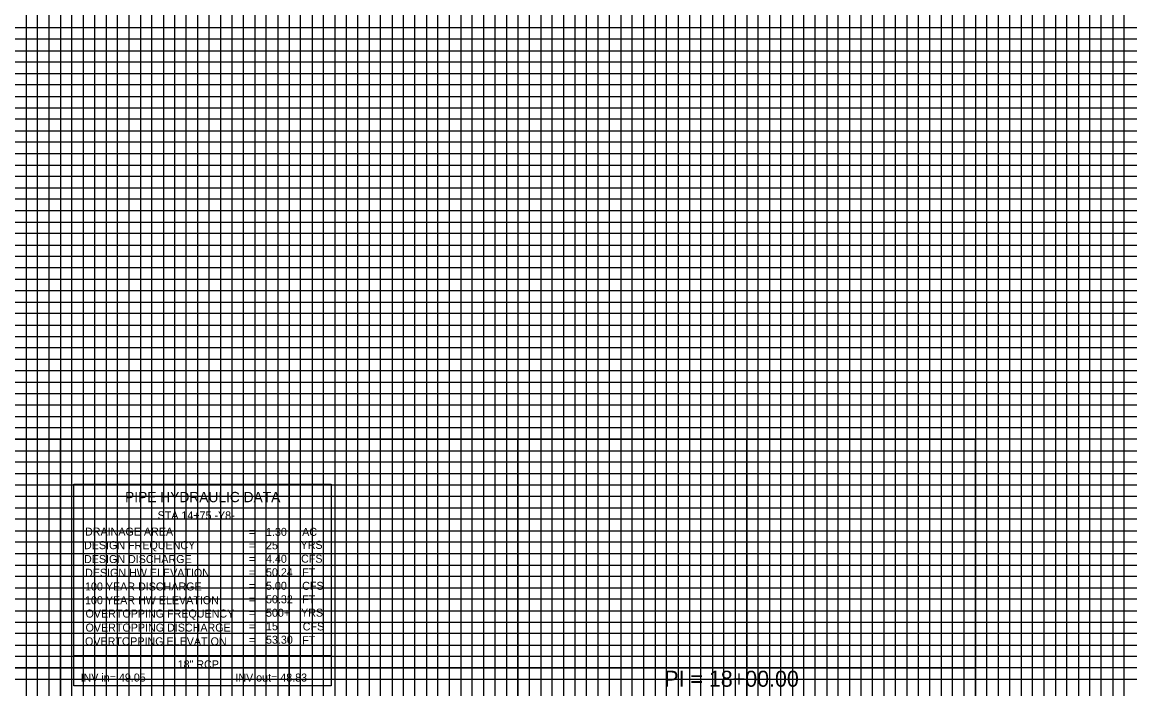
# Model space of a CAD drawing. Extents: x 2345490 to 2436403, y 465165 to 573888.
# Drawn here: x 2382250.1 to 2382734.3, y 541265.3 to 541557 of the extents above; entities that cross this region are included whole.
import ezdxf

# ---------------------------------------------------------------- set-up
doc = ezdxf.new("R2010")
doc.units = 0
for name, color, linetype in [('Old_Level_2', 7, 'Continuous'), ('Old_Level_4', 7, 'Continuous'), ('Old_Level_41', 7, 'Continuous'), ('Old_Level_42', 7, 'Continuous'), ('Old_Level_43', 7, 'Continuous'), ('Old_Level_57', 7, 'Continuous')]:
    doc.layers.add(name, color=color, linetype=linetype)

msp = doc.modelspace()

# ---------------------------------------------------------------- linework, layer by layer
at = {"layer": 'Old_Level_4'}
for p, q in [((2382272.67092, 541354.8205), (2382385.17092, 541354.8205)), ((2382272.67092, 541279.8205), (2382272.67092, 541354.8205)), ((2382385.17092, 541354.8205), (2382385.17092, 541279.8205)), ((2382385.17092, 541279.8205), (2382272.67092, 541279.8205))]:
    msp.add_line(p, q, dxfattribs=at)
msp.add_lwpolyline([(2382272.67092, 541279.8205), (2382385.17092, 541279.8205), (2382385.17092, 541266.6055), (2382272.67092, 541266.6055)], close=True, dxfattribs=at)
at = {"layer": 'Old_Level_41'}
for points in [[(2382241.79875, 541024.5045), (2382291.79875, 541024.5045), (2382291.79875, 542049.5045)], [(2382266.79875, 542049.5045), (2382266.79875, 541024.5045), (2382316.79875, 541024.5045), (2382316.79875, 542049.5045)], [(2382341.79875, 542049.5045), (2382341.79875, 541024.5045), (2382391.79875, 541024.5045), (2382391.79875, 542049.5045)], [(2382366.79875, 542049.5045), (2382366.79875, 541024.5045), (2382416.79875, 541024.5045), (2382416.79875, 542049.5045)], [(2382441.79875, 542049.5045), (2382441.79875, 541024.5045), (2382491.79875, 541024.5045), (2382491.79875, 542049.5045)], [(2382466.79875, 542049.5045), (2382466.79875, 541024.5045), (2382516.79875, 541024.5045), (2382516.79875, 542049.5045)], [(2382541.79875, 542049.5045), (2382541.79875, 541024.5045), (2382591.79875, 541024.5045), (2382591.79875, 542049.5045)], [(2382566.79875, 542049.5045), (2382566.79875, 541024.5045), (2382616.79875, 541024.5045), (2382616.79875, 542049.5045)], [(2382641.79875, 542049.5045), (2382641.79875, 541024.5045), (2382691.79875, 541024.5045), (2382691.79875, 542049.5045)], [(2382666.79875, 542049.5045), (2382666.79875, 541024.5045), (2382716.79875, 541024.5045), (2382716.79875, 542049.5045)], [(2383216.79875, 541549.5045), (2381716.79875, 541549.5045), (2381716.79875, 541499.5045), (2383216.79875, 541499.5045)], [(2383216.79875, 541449.5045), (2381716.79875, 541449.5045), (2381716.79875, 541399.5045), (2383216.79875, 541399.5045)], [(2383216.79875, 541374.5045), (2381716.79875, 541374.5045), (2381716.79875, 541424.5045), (2383216.79875, 541424.5045)], [(2383216.79875, 541349.5045), (2381716.79875, 541349.5045), (2381716.79875, 541299.5045), (2383216.79875, 541299.5045)], [(2383216.79875, 541274.5045), (2381716.79875, 541274.5045), (2381716.79875, 541324.5045), (2383216.79875, 541324.5045)]]:
    msp.add_lwpolyline(points, dxfattribs=at)
at = {"layer": 'Old_Level_42'}
msp.add_lwpolyline([(2383216.79875, 541474.5045), (2381716.79875, 541474.5045), (2381716.79875, 541524.5045), (2383216.79875, 541524.5045)], dxfattribs=at)
at = {"layer": 'Old_Level_43'}
for points in [[(2382251.79875, 542049.5045), (2382251.79875, 541024.5045), (2382256.79875, 541024.5045), (2382256.79875, 542049.5045), (2382261.79875, 542049.5045), (2382261.79875, 541024.5045), (2382271.79875, 541024.5045), (2382271.79875, 542049.5045), (2382276.79875, 542049.5045), (2382276.79875, 541024.5045), (2382281.79875, 541024.5045), (2382281.79875, 542049.5045), (2382286.79875, 542049.5045), (2382286.79875, 541024.5045)], [(2382296.79875, 541024.5045), (2382296.79875, 542049.5045)], [(2382301.79875, 542049.5045), (2382301.79875, 541024.5045), (2382306.79875, 541024.5045), (2382306.79875, 542049.5045)], [(2382311.79875, 542049.5045), (2382311.79875, 541024.5045), (2382321.79875, 541024.5045), (2382321.79875, 542049.5045)], [(2382326.79875, 542049.5045), (2382326.79875, 541024.5045), (2382326.79875, 541024.5045), (2382331.79875, 541024.5045), (2382331.79875, 542049.5045)], [(2382336.79875, 542049.5045), (2382336.79875, 541024.5045), (2382346.79875, 541024.5045), (2382346.79875, 542049.5045)], [(2382351.79875, 542049.5045), (2382351.79875, 541024.5045), (2382356.79875, 541024.5045), (2382356.79875, 542049.5045)], [(2382361.79875, 542049.5045), (2382361.79875, 541024.5045), (2382371.79875, 541024.5045), (2382371.79875, 542049.5045)], [(2382376.79875, 542049.5045), (2382376.79875, 541024.5045), (2382381.79875, 541024.5045), (2382381.79875, 542049.5045)], [(2382386.79875, 542049.5045), (2382386.79875, 541024.5045), (2382396.79875, 541024.5045), (2382396.79875, 542049.5045)], [(2382401.79875, 542049.5045), (2382401.79875, 541024.5045), (2382406.79875, 541024.5045), (2382406.79875, 542049.5045)], [(2382411.79875, 542049.5045), (2382411.79875, 541024.5045), (2382421.79875, 541024.5045), (2382421.79875, 542049.5045)], [(2382426.79875, 542049.5045), (2382426.79875, 541024.5045), (2382431.79875, 541024.5045), (2382431.79875, 542049.5045)], [(2382436.79875, 542049.5045), (2382436.79875, 541024.5045), (2382446.79875, 541024.5045), (2382446.79875, 542049.5045)], [(2382451.79875, 542049.5045), (2382451.79875, 541024.5045), (2382456.79875, 541024.5045), (2382456.79875, 542049.5045)], [(2382461.79875, 542049.5045), (2382461.79875, 541024.5045), (2382471.79875, 541024.5045), (2382471.79875, 542049.5045)], [(2382476.79875, 542049.5045), (2382476.79875, 541024.5045)], [(2382476.79875, 541024.5045), (2382481.79875, 541024.5045), (2382481.79875, 542048.9045)], [(2382486.79875, 542048.9045), (2382486.79875, 541024.5045), (2382496.79875, 541024.5045), (2382496.79875, 542049.5045)], [(2382501.79875, 542049.5045), (2382501.79875, 541024.5045), (2382506.79875, 541024.5045), (2382506.79875, 542049.5045)], [(2382511.79875, 542049.5045), (2382511.79875, 541024.5045), (2382521.79875, 541024.5045), (2382521.79875, 542049.5045)], [(2382526.79875, 542049.5045), (2382526.79875, 541024.5045), (2382531.79875, 541024.5045), (2382531.79875, 542049.5045)], [(2382536.79875, 542049.5045), (2382536.79875, 541024.5045), (2382546.79875, 541024.5045), (2382546.79875, 542049.5045)], [(2382551.79875, 542049.5045), (2382551.79875, 541024.5045), (2382556.79875, 541024.5045), (2382556.79875, 542049.5045)], [(2382561.79875, 542049.5045), (2382561.79875, 541024.5045), (2382571.79875, 541024.5045), (2382571.79875, 542049.5045)], [(2382576.79875, 542049.5045), (2382576.79875, 541024.5045), (2382581.79875, 541024.5045), (2382581.79875, 542049.5045)], [(2382586.79875, 542049.5045), (2382586.79875, 541024.5045), (2382596.79875, 541024.5045), (2382596.79875, 542049.5045)], [(2382601.79875, 542049.5045), (2382601.79875, 541024.5045), (2382606.79875, 541024.5045), (2382606.79875, 542049.5045)], [(2382611.79875, 542049.5045), (2382611.79875, 541024.5045), (2382621.79875, 541024.5045), (2382621.79875, 542049.5045)], [(2382626.79875, 542049.5045), (2382626.79875, 541024.5045), (2382631.79875, 541024.5045), (2382631.79875, 542049.5045)], [(2382636.79875, 542049.5045), (2382636.79875, 541024.5045), (2382646.79875, 541024.5045), (2382646.79875, 542049.5045)], [(2382651.79875, 542049.5045), (2382651.79875, 541024.5045), (2382656.79875, 541024.5045), (2382656.79875, 542049.5045)], [(2382661.79875, 542049.5045), (2382661.79875, 541024.5045), (2382671.79875, 541024.5045), (2382671.79875, 542049.5045)], [(2382676.79875, 542049.5045), (2382676.79875, 541024.5045), (2382681.79875, 541024.5045), (2382681.79875, 542049.5045)], [(2382686.79875, 542049.5045), (2382686.79875, 541024.5045), (2382696.79875, 541024.5045), (2382696.79875, 542049.5045)], [(2382701.79875, 542049.5045), (2382701.79875, 541024.5045), (2382706.79875, 541024.5045), (2382706.79875, 542049.5045)], [(2382711.79875, 542049.5045), (2382711.79875, 541024.5045), (2382721.79875, 541024.5045), (2382721.79875, 542049.5045)], [(2382726.79875, 542049.5045), (2382726.79875, 541024.5045), (2382731.79875, 541024.5045), (2382731.79875, 542049.5045)], [(2383166.79875, 541554.5045), (2381766.79875, 541554.5045), (2381766.79875, 541544.5045), (2383166.79875, 541544.5045)], [(2383166.79875, 541539.5045), (2381766.79875, 541539.5045), (2381766.79875, 541534.5045), (2383166.79875, 541534.5045)], [(2383166.79875, 541529.5045), (2381766.79875, 541529.5045)], [(2381766.79875, 541519.5045), (2383166.79875, 541519.5045)], [(2383166.79875, 541514.5045), (2381766.79875, 541514.5045), (2381766.79875, 541509.5045), (2383166.79875, 541509.5045)], [(2383166.79875, 541504.5045), (2381766.79875, 541504.5045), (2381766.79875, 541494.5045), (2383166.79875, 541494.5045)], [(2383166.79875, 541489.5045), (2381766.79875, 541489.5045), (2381766.79875, 541484.5045), (2383166.79875, 541484.5045)], [(2383166.79875, 541479.5045), (2381766.79875, 541479.5045), (2381766.79875, 541469.5045), (2383166.79875, 541469.5045)], [(2383166.79875, 541464.5045), (2381766.79875, 541464.5045), (2381766.79875, 541459.5045), (2383166.79875, 541459.5045)], [(2383166.79875, 541454.5045), (2381766.79875, 541454.5045), (2381766.79875, 541444.5045), (2383166.79875, 541444.5045)], [(2383166.79875, 541439.5045), (2381766.79875, 541439.5045), (2381766.79875, 541434.5045), (2383166.79875, 541434.5045)], [(2383166.79875, 541429.5045), (2381766.79875, 541429.5045), (2381766.79875, 541419.5045), (2383166.79875, 541419.5045)], [(2383166.79875, 541414.5045), (2381766.79875, 541414.5045), (2381766.79875, 541409.5045), (2383166.79875, 541409.5045)], [(2383166.79875, 541404.5045), (2381766.79875, 541404.5045), (2381766.79875, 541394.5045), (2383166.79875, 541394.5045)], [(2383166.79875, 541389.5045), (2381766.79875, 541389.5045), (2381766.79875, 541384.5045), (2383166.79875, 541384.5045)], [(2383166.79875, 541379.5045), (2381766.79875, 541379.5045), (2381766.79875, 541369.5045), (2383166.79875, 541369.5045)], [(2383166.79875, 541364.5045), (2381766.79875, 541364.5045), (2381766.79875, 541359.5045), (2383166.79875, 541359.5045)], [(2383166.79875, 541354.5045), (2381766.79875, 541354.5045), (2381766.79875, 541344.5045), (2383166.79875, 541344.5045)], [(2383166.79875, 541339.5045), (2381766.79875, 541339.5045), (2381766.79875, 541334.5045), (2383166.79875, 541334.5045)], [(2383166.79875, 541329.5045), (2381766.79875, 541329.5045), (2381766.79875, 541319.5045), (2383166.79875, 541319.5045)], [(2383166.79875, 541314.5045), (2381766.79875, 541314.5045), (2381766.79875, 541309.5045), (2383166.79875, 541309.5045)], [(2383166.79875, 541304.5045), (2381766.79875, 541304.5045), (2381766.79875, 541294.5045), (2383166.79875, 541294.5045)], [(2383166.79875, 541289.5045), (2381766.79875, 541289.5045), (2381766.79875, 541284.5045), (2383166.79875, 541284.5045)], [(2383166.79875, 541279.5045), (2381766.79875, 541279.5045), (2381766.79875, 541269.5045), (2383166.79875, 541269.5045)]]:
    msp.add_lwpolyline(points, dxfattribs=at)
at = {"layer": 'Old_Level_57'}
for p, q in [((2381716.79925, 541374.50475), (2382666.79875, 541374.50475)), ((2382266.79875, 541024.50475), (2382266.79875, 541374.50475)), ((2382266.79875, 541024.60475), (2382266.79875, 541374.50475)), ((2382366.79875, 541024.50475), (2382366.79875, 541374.50475)), ((2382366.79875, 541024.60475), (2382366.79875, 541374.50475)), ((2382466.79875, 541024.50475), (2382466.79875, 541374.50475)), ((2382466.79875, 541024.60475), (2382466.79875, 541374.50475)), ((2382566.79875, 541024.50475), (2382566.79875, 541374.50475)), ((2382566.79875, 541024.60475), (2382566.79875, 541374.50475)), ((2382666.79875, 541024.50475), (2382666.79875, 541374.50475)), ((2381716.79925, 541324.50475), (2382666.79875, 541324.50475)), ((2381716.79925, 541274.50475), (2382666.79875, 541274.50475))]:
    msp.add_line(p, q, dxfattribs=at)

# ---------------------------------------------------------------- texts
at = {"layer": 'Old_Level_2'}
msp.add_text('PI = 18+00.00', height=7.0000005, dxfattribs=at).set_placement((2382530.77674, 541266.26182))
at = {"layer": 'Old_Level_4'}
for s, height, p in [('PIPE HYDRAULIC DATA', 4.49985, (2382295.07092, 541346.9955)), ('STA 14+75 -Y8-', 3.4998, (2382309.29167, 541339.495)), ('DRAINAGE AREA', 3.49995, (2382277.57092, 541332.3705)), ('=        ', 3.49995, (2382349.22092, 541332.2705)), ('1.30', 3.49995, (2382356.68142, 541332.27005)), ('AC', 3.49995, (2382372.49592, 541332.2705)), ('DESIGN FREQUENCY', 3.49995, (2382277.12092, 541326.4455)), ('=        ', 3.49995, (2382349.22092, 541326.3705)), ('25', 3.49995, (2382356.68142, 541326.3701)), ('YRS', 3.49995, (2382371.79592, 541326.5705)), ('4.40', 3.49995, (2382356.68142, 541320.47015)), ('CFS', 3.49995, (2382372.02092, 541320.5455)), ('DESIGN DISCHARGE', 3.49995, (2382277.12092, 541320.3705)), ('=        ', 3.49995, (2382349.22092, 541320.4705)), ('DESIGN HW ELEVATION', 3.49995, (2382277.57092, 541314.3705)), ('=        ', 3.49995, (2382349.22092, 541314.5705)), ('50.24', 3.49995, (2382356.68142, 541314.5702)), ('FT', 3.49995, (2382372.49592, 541314.5705)), ('100 YEAR DISCHARGE', 3.49995, (2382277.57092, 541308.3705)), ('=        ', 3.49995, (2382349.22092, 541308.6705)), ('5.00', 3.49995, (2382356.68142, 541308.67025)), ('CFS', 3.49995, (2382372.49592, 541308.6705)), ('100 YEAR HW ELEVATION', 3.49995, (2382277.57092, 541302.3705)), ('=        ', 3.49995, (2382349.22092, 541302.7705)), ('50.32', 3.49995, (2382356.68142, 541302.7703)), ('FT', 3.49995, (2382372.49592, 541302.7705)), ('OVERTOPPING FREQUENCY', 3.49995, (2382277.79592, 541296.5205)), ('500+', 3.49995, (2382356.68142, 541296.87035)), ('YRS', 3.49995, (2382372.02092, 541296.9205)), ('=        ', 3.49995, (2382349.22092, 541296.8705)), ('OVERTOPPING DISCHARGE', 3.49995, (2382277.79592, 541290.3955)), ('=        ', 3.49995, (2382349.22092, 541290.9705)), ('15', 3.49995, (2382356.68142, 541290.9704)), ('CFS', 3.49995, (2382372.72092, 541290.8955)), ('OVERTOPPING ELEVATION', 3.49995, (2382277.57092, 541284.3705)), ('=        ', 3.49995, (2382349.22092, 541285.0705)), ('53.30', 3.49995, (2382356.68142, 541285.07045)), ('FT', 3.49995, (2382372.49592, 541284.8705)), ('18" RCP', 3.4998, (2382318.06017, 541274.32325)), ('INV in= 49.05', 3.4998, (2382275.60342, 541268.5325)), ('INV out= 48.83', 3.4998, (2382343.28017, 541268.5325))]:
    msp.add_text(s, height=height, dxfattribs=at).set_placement(p)

doc.saveas('drawing.dxf')
